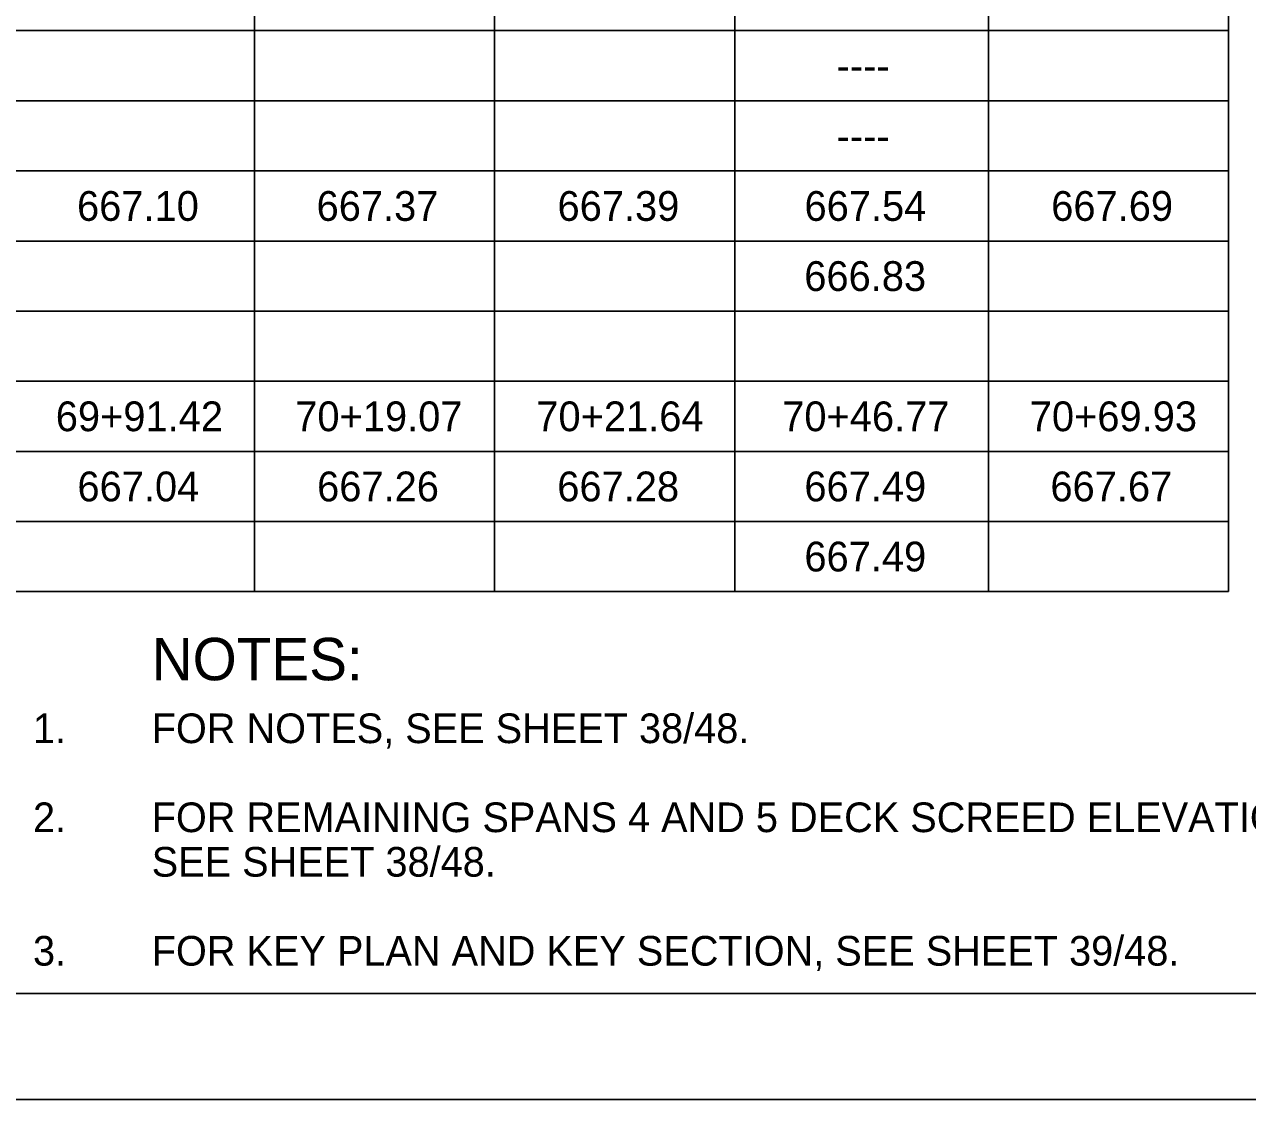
# Model space of a CAD drawing. Extents: x 0 to 34, y 0 to 22.
# Drawn here: x 24.99 to 30.76, y 0 to 5.07 of the extents above; entities that cross this region are included whole.
import ezdxf

# ---------------------------------------------------------------- set-up
doc = ezdxf.new("R2010")
doc.units = 0
for name, color, linetype in [('BR_P_Gen_Text', 7, 'Continuous'), ('SH_Border', 7, 'Continuous'), ('SH_Cut_Line', 7, 'Continuous'), ('SH_Text', 7, 'Continuous')]:
    doc.layers.add(name, color=color, linetype=linetype)

msp = doc.modelspace()

# ---------------------------------------------------------------- linework, layer by layer
at = {"layer": 'SH_Border'}
msp.add_lwpolyline([(1.5, 21.5), (33.5, 21.5), (33.5, 0.5), (1.5, 0.5)], close=True, dxfattribs=at)
at = {"layer": 'SH_Cut_Line'}
msp.add_lwpolyline([(0, 0), (34, 0), (34, 22), (0, 22)], close=True, dxfattribs=at)
at = {"layer": 'SH_Text'}
for p, q in [((30.6725, 21.2971), (30.6725, 2.3971)), ((26.078, 20.1135), (26.078, 2.3971)), ((27.2107, 20.1135), (27.2107, 2.3971)), ((28.3434, 20.1135), (28.3434, 2.3971)), ((29.5398, 20.1135), (29.5398, 2.3971)), ((4.1998, 5.0444), (30.6725, 5.0444)), ((4.1998, 4.7135), (30.6725, 4.7135)), ((4.1998, 4.3826), (30.6725, 4.3826)), ((4.1998, 4.0516), (30.6725, 4.0516)), ((2.7998, 3.7207), (30.6725, 3.7207)), ((2.7998, 3.3898), (30.6725, 3.3898)), ((4.1998, 3.0589), (30.6725, 3.0589)), ((4.1998, 2.728), (30.6725, 2.728)), ((2.7998, 2.3971), (30.6725, 2.3971))]:
    msp.add_line(p, q, dxfattribs=at)

# ---------------------------------------------------------------- texts
at = {"layer": 'BR_P_Gen_Text'}
for s, height, p in [('NOTES:', 0.2, (25.5929, 1.9788)), ('1.   ', 0.14, (25.0329, 1.682)), ('FOR NOTES, SEE SHEET 38/48.', 0.14, (25.5929, 1.682)), ('2.   ', 0.14, (25.0329, 1.262)), ('FOR REMAINING SPANS 4 AND 5 DECK SCREED ELEVATIONS,', 0.14, (25.5929, 1.262)), ('SEE SHEET 38/48.', 0.14, (25.5929, 1.052)), ('3.', 0.14, (25.0329, 0.632)), ('FOR KEY PLAN AND KEY SECTION, SEE SHEET 39/48.', 0.14, (25.5929, 0.632))]:
    msp.add_text(s, height=height, dxfattribs=at).set_placement(p)
at = {"layer": 'SH_Text'}
for s, p in [('----', (28.8239, 4.8087)), ('----', (28.8239, 4.4778)), ('667.10', (25.2407, 4.1468)), ('667.37', (26.3708, 4.1468)), ('667.39', (27.5074, 4.1468)), ('667.54', (28.6726, 4.1468)), ('667.69', (29.8365, 4.1468)), ('666.83', (28.6715, 3.8159)), ('69+91.42', (25.1404, 3.1541)), ('70+19.07', (26.2701, 3.1541)), ('70+21.64', (27.4074, 3.1541)), ('70+46.77', (28.5674, 3.1541)), ('70+69.93', (29.7353, 3.1541)), ('667.04', (25.2426, 2.8232)), ('667.26', (26.3733, 2.8232)), ('667.28', (27.5063, 2.8232)), ('667.49', (28.672, 2.8232)), ('667.67', (29.8326, 2.8232)), ('667.49', (28.672, 2.4923))]:
    msp.add_text(s, height=0.14051, dxfattribs=at).set_placement(p)

doc.saveas('drawing.dxf')
